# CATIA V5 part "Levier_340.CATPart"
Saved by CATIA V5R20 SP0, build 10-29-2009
Part number: Levier_340
Bounding box of the stored display mesh (mm): x -20 to 20, y -65 to 305, z -15 to 15
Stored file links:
  D:\thinkmotion-MPB\Dropbox\IAO_2011\MMS_GR3\aweinling\aweinling\Levier_340.CATPart
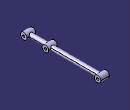
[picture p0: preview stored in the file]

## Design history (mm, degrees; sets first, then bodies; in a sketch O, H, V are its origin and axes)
Parameters
  `Longueur L1` = 100 mm
  `Longueur L2` = 240 mm
  `Largeur La` = 40 mm
  D_Bielle = 20 mm
  D_Trou = 10 mm
  D_Pivot = 30 mm
Body1 (main body)
  Sketch1 on yz-plane, origin (0, 0, 0), H (0, 1, 0), V (0, 0, 1)
    circle A1 centre (50, 0) radius 15
    point P1 (50, 0)
    point P2 (-50, 0)
    circle A2 centre (-50, 0) radius 15
    circle A3 centre (290, 0) radius 15
    point P3 (290, 0)
    radius A1 = 15 {= D_Pivot /2}
    distance P2 P1 = 100 {= `Longueur L1`}
    radius A3 = 15 {= D_Pivot /2}
    distance P1 P3 = 240 {= `Longueur L2`}
    coincidence: P1 H, P3 H
    symmetry: A1 A2 V
  Pad1: profile Sketch1, direction (1, 0, 0), length 20 {= `Largeur La` /2}, mirrored extent
  Sketch2 on zx-plane, origin (0, 0, 0), H (-1, 0, 0), V (0, 0, 1)
    circle A1 centre (0, 0) radius 10
    radius A1 = 10 {= D_Bielle /2}
  Pad2: profile Sketch2, direction (0, 1, 0), length 50 {= `Longueur L1` /2}, mirrored extent
  Sketch3 on xy-plane, origin (0, 0, 0), H (1, 0, 0), V (0, 1, 0)
    line L1 (0, 280) -> (10, 280)
    line L2 (10, 280) -> (10, 40)
    line L3 (10, 40) -> (0, 40)
    line L4 (0, 40) -> (0, 280)
    distance L2 L4 = 10 {= D_Bielle /2}
    distance L3 L1 = 240 {= `Longueur L2`}
    horizontal: L1 H, L3 H
    vertical: L2 V, L4 V
  Shaft1: profile Sketch3, axis Sketch3.L4, angle 360
  Sketch4 on start face of Pad1, origin (-20, -41.4204, -2.1508), H (0, 1, 0), V (0, 0, -1)
    point P1 (-8.5796, -2.1508)
    reference projected circle E1 centre (-8.5796, -2.1508) radius 15 from edge [start face of Pad1 | face of Pad1 from Sketch1.A2]
    concentricity: P1 E1
  Hole1: placed by Sketch4, at (-20, -50, 0) direction (1, 0, 0), diameter 10 {= D_Trou}, through (limit type 6)
  Sketch5 on start face of Pad1, origin (-20, 41.183, -2.5631), H (0, 1, 0), V (0, 0, -1)
    point P1 (8.817, -2.5631)
    reference projected circle E1 centre (8.817, -2.5631) radius 15 from edge [start face of Pad1 | face of Pad1 from Sketch1.A1]
    concentricity: E1 P1
  Hole2: placed by Sketch5, at (-20, 50, 0) direction (1, 0, 0), diameter 10 {= D_Trou}, through (limit type 6)
  Sketch6 on start face of Pad1, origin (-20, 194.14, 1.7201), H (0, 1, 0), V (0, 0, -1)
    point P1 (95.86, 1.7201)
    reference projected circle E1 centre (95.86, 1.7201) radius 15 from edge [start face of Pad1 | face of Pad1 from Sketch1.A3]
    concentricity: P1 E1
  Hole3: placed by Sketch6, at (-20, 290, 0) direction (1, 0, 0), diameter 10 {= D_Trou}, through (limit type 6)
